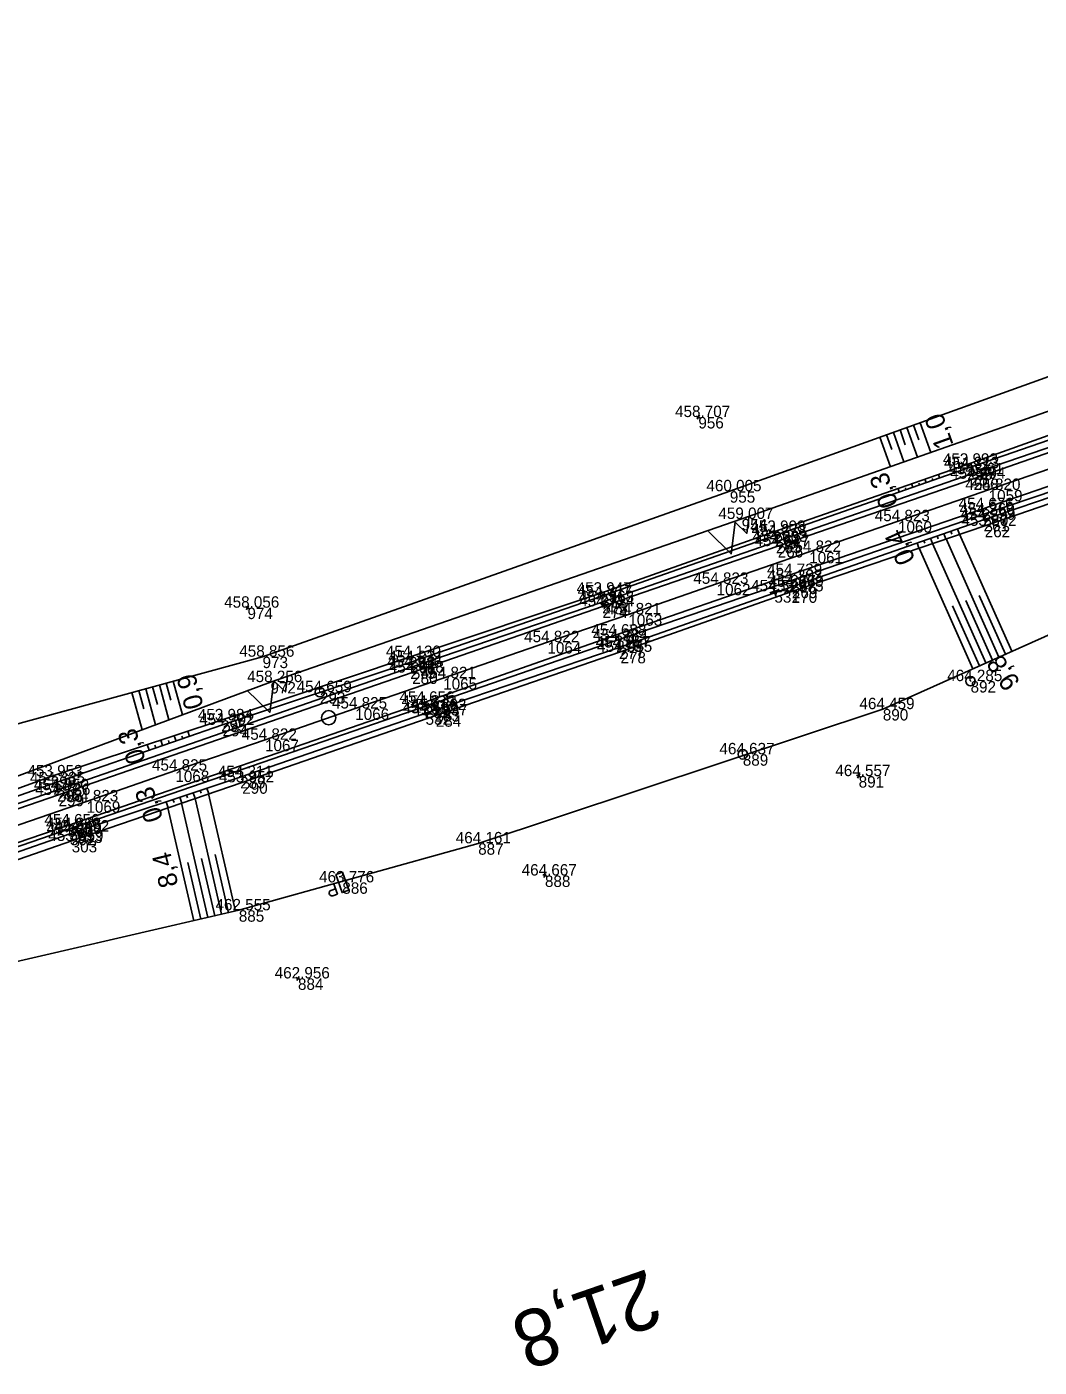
# Model space of a CAD drawing. Extents: x -751615 to -750797, y -1114905 to -1114561.
# Drawn here: x -751423 to -751316.4, y -1114841.6 to -1114700.6 of the extents above; entities that cross this region are included whole.
import ezdxf

# ---------------------------------------------------------------- set-up
doc = ezdxf.new("R2010")
doc.units = 0
for name, color, linetype in [('Vrstva 1', 7, 'Continuous'), ('Vrstva 33', 7, 'Continuous'), ('Vrstva 4', 7, 'Continuous'), ('Vrstva 48', 7, 'Continuous'), ('Vrstva 49', 7, 'Continuous'), ('Vrstva 50', 7, 'Continuous'), ('Vrstva 53', 7, 'Continuous'), ('Vrstva 60', 7, 'Continuous'), ('Vrstva 61', 7, 'Continuous'), ('Vrstva 7', 7, 'Continuous')]:
    doc.layers.add(name, color=color, linetype=linetype)

msp = doc.modelspace()

# ---------------------------------------------------------------- linework, layer by layer
at = {"layer": 'Vrstva 1'}
msp.add_lwpolyline([(-751207.29, -1114709.83), (-751216.51, -1114713.01), (-751226.43, -1114716.44), (-751236.32, -1114719.85), (-751245.85, -1114723.14), (-751255.29, -1114726.39), (-751264.7, -1114729.64), (-751273.96, -1114732.84), (-751283.46, -1114736.11), (-751293.11, -1114739.44), (-751302.88, -1114742.81), (-751312.19, -1114746.02), (-751321.76, -1114749.32), (-751331.3, -1114752.61), (-751340.65, -1114755.84), (-751350.4, -1114759.2), (-751359.69, -1114762.41), (-751368.21, -1114765.34), (-751379.18, -1114769.13), (-751388.44, -1114772.32), (-751397.94, -1114775.61), (-751407.38, -1114778.86), (-751416.74, -1114782.09), (-751426.63, -1114785.5)], dxfattribs=at)
at = {"layer": 'Vrstva 33'}
msp.add_lwpolyline([(-751389.12, -1114791.45), (-751389.82, -1114791.7), (-751390.48, -1114789.79), (-751389.77, -1114789.55)], close=True, dxfattribs=at)
for points in [[(-751390.8, -1114792.04), (-751390.97, -1114792.04), (-751391.14, -1114791.89), (-751391.18, -1114791.78), (-751391.14, -1114791.55), (-751391.01, -1114791.46)], [(-751391.01, -1114791.46), (-751390.51, -1114791.29)], [(-751390.72, -1114790.69), (-751390.31, -1114791.87)], [(-751390.31, -1114791.87), (-751390.8, -1114792.04)]]:
    msp.add_lwpolyline(points, dxfattribs=at)
at = {"layer": 'Vrstva 4'}
for points in [[(-751187.89, -1114700.58), (-751206.03, -1114707.04), (-751231.23, -1114715.6), (-751249.54, -1114721.97), (-751267.72, -1114728.47), (-751285.3, -1114734.54), (-751305.69, -1114741.51), (-751323.63, -1114747.67), (-751344.16, -1114754.78), (-751362.44, -1114761.12), (-751382.65, -1114768), (-751419.83, -1114780.91), (-751439.84, -1114787.75), (-751459.65, -1114794.56), (-751479.26, -1114801.4), (-751499.56, -1114808.3), (-751517.66, -1114814.61), (-751524.47, -1114817.14), (-751524.91, -1114817.65)], [(-751186.45, -1114705.27), (-751204.57, -1114711.26), (-751229.26, -1114719.97), (-751248.51, -1114726.39), (-751266.03, -1114732.59), (-751283.83, -1114738.73), (-751304.21, -1114745.77), (-751322.37, -1114751.9), (-751342.61, -1114758.9), (-751360.96, -1114765.17), (-751381.11, -1114772.12), (-751418.54, -1114785), (-751438.61, -1114791.91), (-751458.17, -1114798.66), (-751477.81, -1114805.42), (-751497.9, -1114812.48), (-751516.51, -1114818.69), (-751522.39, -1114820.61), (-751523.2, -1114820.52)], [(-751205.8, -1114707.6), (-751230.97, -1114716.26), (-751249.42, -1114722.68), (-751267.45, -1114728.87), (-751285.11, -1114734.87), (-751305.56, -1114741.94), (-751323.35, -1114748.14), (-751343.96, -1114755.23), (-751362.41, -1114761.58), (-751382.45, -1114768.54), (-751419.68, -1114781.41), (-751439.79, -1114788.3), (-751459.37, -1114795.06), (-751479.15, -1114801.88), (-751499.34, -1114808.87), (-751517.57, -1114815.16), (-751524.91, -1114817.65)], [(-751204.68, -1114710.75), (-751229.56, -1114719.28), (-751248.53, -1114725.94), (-751266.25, -1114732.04), (-751284.07, -1114738.15), (-751304.21, -1114745.08), (-751322.47, -1114751.34), (-751342.64, -1114758.27), (-751361.14, -1114764.64), (-751381.34, -1114771.71), (-751418.71, -1114784.62), (-751438.73, -1114791.47), (-751458.26, -1114798.22), (-751477.95, -1114805), (-751498.18, -1114811.91), (-751516.63, -1114818.24), (-751523.2, -1114820.52)]]:
    msp.add_lwpolyline(points, dxfattribs=at)
at = {"layer": 'Vrstva 48'}
for p, q in [((-751331.79, -1114743.26), (-751330.68, -1114746.37)), ((-751331.09, -1114743.01), (-751330.53, -1114744.56)), ((-751330.38, -1114742.75), (-751329.26, -1114745.87)), ((-751329.68, -1114742.5), (-751329.11, -1114744.06)), ((-751328.97, -1114742.25), (-751327.84, -1114745.38)), ((-751333.21, -1114743.77), (-751332.09, -1114746.87)), ((-751332.5, -1114743.52), (-751331.94, -1114745.07)), ((-751326.92, -1114748.05), (-751327.05, -1114747.68)), ((-751330.46, -1114749.29), (-751330.52, -1114749.1)), ((-751329.75, -1114749.04), (-751329.88, -1114748.67)), ((-751329.04, -1114748.8), (-751329.11, -1114748.61)), ((-751328.33, -1114748.55), (-751328.47, -1114748.17)), ((-751327.63, -1114748.3), (-751327.69, -1114748.11)), ((-751331.17, -1114749.54), (-751331.3, -1114749.16)), ((-751328.58, -1114754.66), (-751328.49, -1114754.93)), ((-751327.88, -1114754.41), (-751327.68, -1114754.97)), ((-751327.17, -1114754.16), (-751327.07, -1114754.45)), ((-751326.46, -1114753.91), (-751326.26, -1114754.49)), ((-751320.67, -1114766.91), (-751326.23, -1114754.48)), ((-751325.75, -1114753.67), (-751325.65, -1114753.96)), ((-751325.04, -1114753.42), (-751324.84, -1114754.01)), ((-751319.3, -1114766.3), (-751324.81, -1114753.99)), ((-751329.29, -1114754.9), (-751329.1, -1114755.45)), ((-751323.41, -1114768.14), (-751329.09, -1114755.45)), ((-751322.04, -1114767.53), (-751327.66, -1114754.96)), ((-751319.99, -1114766.61), (-751322.75, -1114760.42)), ((-751322.73, -1114767.83), (-751325.55, -1114761.52)), ((-751321.36, -1114767.22), (-751324.15, -1114760.97)), ((-751410.5, -1114770.24), (-751409.46, -1114774.03)), ((-751409.78, -1114770.04), (-751409.27, -1114771.9)), ((-751409.05, -1114769.84), (-751408.05, -1114773.51)), ((-751408.33, -1114769.64), (-751407.84, -1114771.44)), ((-751407.61, -1114769.45), (-751406.64, -1114772.98)), ((-751411.95, -1114770.64), (-751410.87, -1114774.55)), ((-751411.22, -1114770.44), (-751410.7, -1114772.36)), ((-751408.72, -1114776.23), (-751408.91, -1114775.65)), ((-751408.02, -1114775.98), (-751408.11, -1114775.7)), ((-751407.31, -1114775.74), (-751407.49, -1114775.18)), ((-751406.6, -1114775.49), (-751406.69, -1114775.22)), ((-751405.89, -1114775.25), (-751406.06, -1114774.71)), ((-751410.14, -1114776.72), (-751410.34, -1114776.12)), ((-751409.43, -1114776.47), (-751409.53, -1114776.18)), ((-751406.2, -1114781.41), (-751406.1, -1114781.72)), ((-751405.49, -1114781.18), (-751405.29, -1114781.79)), ((-751404.78, -1114780.94), (-751404.68, -1114781.24)), ((-751404.07, -1114780.7), (-751403.87, -1114781.3)), ((-751401.04, -1114793.64), (-751403.89, -1114781.31)), ((-751408.34, -1114782.13), (-751408.12, -1114782.77)), ((-751405.43, -1114794.65), (-751408.16, -1114782.78)), ((-751407.63, -1114781.89), (-751407.52, -1114782.21)), ((-751406.91, -1114781.65), (-751406.71, -1114782.28)), ((-751403.97, -1114794.31), (-751406.74, -1114782.29)), ((-751402.51, -1114793.98), (-751405.31, -1114781.8)), ((-751404.7, -1114794.48), (-751406.07, -1114788.51)), ((-751403.24, -1114794.14), (-751404.63, -1114788.09)), ((-751401.77, -1114793.81), (-751403.19, -1114787.68))]:
    msp.add_line(p, q, dxfattribs=at)
at = {"layer": 'Vrstva 49'}
for p, q in [((-751352.09, -1114741.76), (-751352.54, -1114741.54)), ((-751352.21, -1114741.42), (-751352.43, -1114741.87)), ((-751399.56, -1114761.82), (-751400.01, -1114761.6)), ((-751399.68, -1114761.49), (-751399.9, -1114761.93)), ((-751335.22, -1114779.55), (-751335.67, -1114779.33)), ((-751335.33, -1114779.21), (-751335.55, -1114779.66)), ((-751368.24, -1114790.01), (-751368.69, -1114789.79)), ((-751368.36, -1114789.67), (-751368.58, -1114790.12)), ((-751394.24, -1114800.84), (-751394.69, -1114800.62)), ((-751394.36, -1114800.51), (-751394.58, -1114800.96))]:
    msp.add_line(p, q, dxfattribs=at)
for points in [[(-751234.95, -1114713.28), (-751245.48, -1114717.14), (-751281.47, -1114726.53), (-751304.18, -1114733.33), (-751349.01, -1114749.46), (-751398.2, -1114766.87), (-751445.8, -1114779.91), (-751491.92, -1114801.09), (-751522.47, -1114813.15), (-751523.88, -1114811.23), (-751530.06, -1114804.52)], [(-751231.53, -1114714.48), (-751249.64, -1114721.46), (-751267.89, -1114727.82), (-751285.51, -1114733.95), (-751305.91, -1114740.8), (-751324, -1114747.03), (-751344.27, -1114754.11), (-751362.59, -1114760.52), (-751382.59, -1114767.44), (-751402.41, -1114774.04), (-751420.23, -1114780.2), (-751439.89, -1114787.15), (-751459.92, -1114794.04), (-751479.47, -1114800.49), (-751499.79, -1114807.5), (-751517.87, -1114814.1), (-751523.11, -1114815.97), (-751524.21, -1114815.64), (-751526.18, -1114811.44)], [(-751244.9, -1114718.57), (-751249.94, -1114720.63), (-751268.48, -1114726.93), (-751276.66, -1114729.62), (-751285.76, -1114733.33), (-751305.98, -1114740.17), (-751324.13, -1114746.66), (-751344.39, -1114753.73), (-751362.68, -1114760.23), (-751382.77, -1114766.9), (-751402.56, -1114773.56), (-751420.5, -1114779.46), (-751440.12, -1114786.64), (-751460.29, -1114793.37), (-751479.7, -1114799.99), (-751499.94, -1114807), (-751518.24, -1114813.43), (-751522.74, -1114814.82), (-751523.67, -1114814.11), (-751524.93, -1114811.32)], [(-751523.9, -1114821.95), (-751516.26, -1114819.37), (-751497.39, -1114813.06), (-751477.62, -1114806.13), (-751458.02, -1114799.12), (-751438.43, -1114792.47), (-751418.48, -1114785.51), (-751400.56, -1114779.53), (-751380.1, -1114772.49), (-751360.67, -1114765.9), (-751342.47, -1114759.51), (-751322.29, -1114752.46), (-751304.11, -1114746.3), (-751283.78, -1114739.21), (-751265.74, -1114733.22), (-751248.29, -1114727.04), (-751240.07, -1114724.3)], [(-751204.75, -1114724.61), (-751227.2, -1114725.51), (-751238.2, -1114726.49), (-751253.2, -1114735.38), (-751297.85, -1114756.71), (-751332.9, -1114772.39), (-751375.5, -1114786.51), (-751400.7, -1114793.56), (-751443.21, -1114803.36), (-751482.54, -1114812.28)], [(-751240.24, -1114725.65), (-751248.02, -1114728.05), (-751265.49, -1114734.04), (-751283.47, -1114739.99), (-751303.76, -1114746.77), (-751322.17, -1114753.1), (-751342.49, -1114760), (-751360.52, -1114766.36), (-751379.96, -1114773.04), (-751400.34, -1114780.09), (-751418.29, -1114786.26), (-751438.17, -1114793.17), (-751457.68, -1114799.96), (-751477.22, -1114807.06), (-751497.38, -1114813.97), (-751516.22, -1114820.45), (-751522.92, -1114822.93), (-751523.9, -1114821.95)], [(-751276.66, -1114729.62), (-751280.14, -1114730.3), (-751302.67, -1114736.54), (-751347.76, -1114752.37), (-751397.37, -1114769.54), (-751443.61, -1114786.7), (-751459.32, -1114792.11), (-751460.29, -1114793.37)]]:
    msp.add_lwpolyline(points, dxfattribs=at)
at = {"layer": 'Vrstva 50'}
for points in [[(-751347.01, -1114752.23), (-751347.23, -1114753.9), (-751348.43, -1114752.72), (-751348.87, -1114756.05), (-751351.26, -1114753.7)], [(-751395.58, -1114768.92), (-751395.8, -1114770.58), (-751397, -1114769.41), (-751397.44, -1114772.73), (-751399.84, -1114770.38)]]:
    msp.add_lwpolyline(points, dxfattribs=at)
at = {"layer": 'Vrstva 53'}
for p, q in [((-751323.61, -1114769.42), (-751323.71, -1114769.46)), ((-751347.6, -1114777.12), (-751347.69, -1114777.15))]:
    msp.add_line(p, q, dxfattribs=at)
for centre in [(-751323.66, -1114769.44), (-751347.64, -1114777.14)]:
    msp.add_circle(centre, 0.499, dxfattribs=at)
at = {"layer": 'Vrstva 60'}
for p, q in [((-751352.32, -1114741.65), (-751352.32, -1114741.65)), ((-751324.13, -1114746.66), (-751324.13, -1114746.66)), ((-751324, -1114747.03), (-751324, -1114747.03)), ((-751323.63, -1114747.67), (-751323.63, -1114747.67)), ((-751323.35, -1114748.14), (-751323.35, -1114748.14)), ((-751349.01, -1114749.46), (-751349.01, -1114749.46)), ((-751321.76, -1114749.32), (-751321.76, -1114749.32)), ((-751322.47, -1114751.34), (-751322.47, -1114751.34)), ((-751322.37, -1114751.9), (-751322.37, -1114751.9)), ((-751347.76, -1114752.37), (-751347.76, -1114752.37)), ((-751331.3, -1114752.61), (-751331.3, -1114752.61)), ((-751322.29, -1114752.46), (-751322.29, -1114752.46)), ((-751322.17, -1114753.1), (-751322.17, -1114753.1)), ((-751344.39, -1114753.73), (-751344.39, -1114753.73)), ((-751344.27, -1114754.11), (-751344.27, -1114754.11)), ((-751344.16, -1114754.78), (-751344.16, -1114754.78)), ((-751343.96, -1114755.23), (-751343.96, -1114755.23)), ((-751340.65, -1114755.84), (-751340.65, -1114755.84)), ((-751342.64, -1114758.27), (-751342.64, -1114758.27)), ((-751342.61, -1114758.9), (-751342.61, -1114758.9)), ((-751362.68, -1114760.23), (-751362.68, -1114760.23)), ((-751350.4, -1114759.2), (-751350.4, -1114759.2)), ((-751344.31, -1114759.98), (-751344.31, -1114759.98)), ((-751342.49, -1114760), (-751342.49, -1114760)), ((-751342.47, -1114759.51), (-751342.47, -1114759.51)), ((-751399.79, -1114761.71), (-751399.79, -1114761.71)), ((-751362.59, -1114760.52), (-751362.59, -1114760.52)), ((-751362.44, -1114761.12), (-751362.44, -1114761.12)), ((-751362.41, -1114761.58), (-751362.41, -1114761.58)), ((-751359.69, -1114762.41), (-751359.69, -1114762.41)), ((-751361.14, -1114764.64), (-751361.14, -1114764.64)), ((-751368.21, -1114765.34), (-751368.21, -1114765.34)), ((-751360.96, -1114765.17), (-751360.96, -1114765.17)), ((-751360.67, -1114765.9), (-751360.67, -1114765.9)), ((-751398.2, -1114766.87), (-751398.2, -1114766.87)), ((-751382.77, -1114766.9), (-751382.77, -1114766.9)), ((-751382.59, -1114767.44), (-751382.59, -1114767.44)), ((-751360.52, -1114766.36), (-751360.52, -1114766.36)), ((-751382.65, -1114768), (-751382.65, -1114768)), ((-751382.45, -1114768.54), (-751382.45, -1114768.54)), ((-751397.37, -1114769.54), (-751397.37, -1114769.54)), ((-751379.18, -1114769.13), (-751379.18, -1114769.13)), ((-751323.66, -1114769.44), (-751323.66, -1114769.44)), ((-751392.16, -1114770.6), (-751392.16, -1114770.6)), ((-751381.34, -1114771.71), (-751381.34, -1114771.71)), ((-751388.44, -1114772.32), (-751388.44, -1114772.32)), ((-751381.11, -1114772.12), (-751381.11, -1114772.12)), ((-751381.04, -1114772.83), (-751381.04, -1114772.83)), ((-751380.1, -1114772.49), (-751380.1, -1114772.49)), ((-751379.96, -1114773.04), (-751379.96, -1114773.04)), ((-751332.9, -1114772.39), (-751332.9, -1114772.39)), ((-751402.56, -1114773.56), (-751402.56, -1114773.56)), ((-751402.41, -1114774.04), (-751402.41, -1114774.04)), ((-751397.94, -1114775.61), (-751397.94, -1114775.61)), ((-751347.64, -1114777.14), (-751347.64, -1114777.14)), ((-751420.5, -1114779.46), (-751420.5, -1114779.46)), ((-751407.38, -1114778.86), (-751407.38, -1114778.86)), ((-751400.56, -1114779.53), (-751400.56, -1114779.53)), ((-751400.34, -1114780.09), (-751400.34, -1114780.09)), ((-751335.44, -1114779.44), (-751335.44, -1114779.44)), ((-751420.23, -1114780.2), (-751420.23, -1114780.2)), ((-751419.83, -1114780.91), (-751419.83, -1114780.91)), ((-751419.68, -1114781.41), (-751419.68, -1114781.41)), ((-751416.74, -1114782.09), (-751416.74, -1114782.09)), ((-751418.71, -1114784.62), (-751418.71, -1114784.62)), ((-751418.54, -1114785), (-751418.54, -1114785)), ((-751418.48, -1114785.51), (-751418.48, -1114785.51)), ((-751417.71, -1114785.27), (-751417.71, -1114785.27)), ((-751418.29, -1114786.26), (-751418.29, -1114786.26)), ((-751375.5, -1114786.51), (-751375.5, -1114786.51)), ((-751368.47, -1114789.9), (-751368.47, -1114789.9)), ((-751389.8, -1114790.62), (-751389.8, -1114790.62)), ((-751400.7, -1114793.56), (-751400.7, -1114793.56)), ((-751394.47, -1114800.73), (-751394.47, -1114800.73))]:
    msp.add_line(p, q, dxfattribs=at)
at = {"layer": 'Vrstva 7'}
for p, q in [((-751343.84, -1114759.82), (-751344.78, -1114760.14)), ((-751344.15, -1114760.45), (-751344.47, -1114759.51)), ((-751392.11, -1114770.58), (-751392.2, -1114770.61)), ((-751380.57, -1114772.67), (-751381.51, -1114772.99)), ((-751380.88, -1114773.3), (-751381.2, -1114772.36)), ((-751417.23, -1114785.11), (-751418.18, -1114785.44)), ((-751417.54, -1114785.75), (-751417.87, -1114784.8))]:
    msp.add_line(p, q, dxfattribs=at)
for centre, radius in [((-751392.16, -1114770.6), 0.5), ((-751391.23, -1114773.29), 0.75)]:
    msp.add_circle(centre, radius, dxfattribs=at)

# ---------------------------------------------------------------- texts
at = {"layer": 'Vrstva 48'}
for s, rotation, p in [('1,0', 109.7893, (-751325.42, -1114744.57)), ('0,3', 109.2497, (-751331.25, -1114750.82)), ('0,4', 114.252, (-751329.44, -1114756.65)), ('9,8', 123.7534, (-751318.37, -1114769.56)), ('0,9', 105.316, (-751404.38, -1114772.09)), ('0,3', 108.2047, (-751410.46, -1114777.78)), ('0,3', 108.434, (-751408.63, -1114783.9)), ('8,4', 103.9571, (-751407.05, -1114790.89))]:
    msp.add_text(s, height=2, rotation=rotation, dxfattribs=at).set_placement(p)
at = {"layer": 'Vrstva 60'}
for s, p in [('956', (-751352.32, -1114742.85)), ('255', (-751324.13, -1114747.86)), ('256', (-751324, -1114748.24)), ('257', (-751323.63, -1114748.87)), ('258', (-751323.35, -1114749.33)), ('955', (-751349.01, -1114750.66)), ('1059', (-751321.76, -1114750.52)), ('259', (-751322.47, -1114752.54)), ('260', (-751322.37, -1114753.1)), ('954', (-751347.76, -1114753.57)), ('1060', (-751331.3, -1114753.81)), ('261', (-751322.29, -1114753.66)), ('262', (-751322.17, -1114754.3)), ('263', (-751344.39, -1114754.93)), ('264', (-751344.27, -1114755.31)), ('265', (-751344.16, -1114755.99)), ('266', (-751343.96, -1114756.43)), ('1061', (-751340.65, -1114757.04)), ('267', (-751342.64, -1114759.47)), ('268', (-751342.61, -1114760.1)), ('271', (-751362.68, -1114761.43)), ('1062', (-751350.4, -1114760.4)), ('531', (-751344.31, -1114761.18)), ('270', (-751342.49, -1114761.2)), ('269', (-751342.47, -1114760.71)), ('974', (-751399.79, -1114762.91)), ('272', (-751362.59, -1114761.72)), ('273', (-751362.44, -1114762.32)), ('274', (-751362.41, -1114762.78)), ('1063', (-751359.69, -1114763.61)), ('275', (-751361.14, -1114765.84)), ('1064', (-751368.21, -1114766.54)), ('276', (-751360.96, -1114766.37)), ('277', (-751360.67, -1114767.1)), ('973', (-751398.2, -1114768.07)), ('292', (-751382.77, -1114768.1)), ('291', (-751382.59, -1114768.64)), ('278', (-751360.52, -1114767.56)), ('279', (-751382.65, -1114769.2)), ('280', (-751382.45, -1114769.74)), ('972', (-751397.37, -1114770.74)), ('1065', (-751379.18, -1114770.33)), ('892', (-751323.66, -1114770.64)), ('293', (-751392.16, -1114771.8)), ('281', (-751381.34, -1114772.91)), ('1066', (-751388.44, -1114773.52)), ('282', (-751381.11, -1114773.32)), ('532', (-751381.04, -1114774.03)), ('283', (-751380.1, -1114773.69)), ('284', (-751379.96, -1114774.24)), ('890', (-751332.9, -1114773.58)), ('295', (-751402.56, -1114774.76)), ('294', (-751402.41, -1114775.25)), ('1067', (-751397.94, -1114776.81)), ('889', (-751347.64, -1114778.34)), ('296', (-751420.5, -1114780.66)), ('297', (-751420.23, -1114781.4)), ('1068', (-751407.38, -1114780.06)), ('289', (-751400.56, -1114780.73)), ('290', (-751400.34, -1114781.29)), ('891', (-751335.44, -1114780.64)), ('298', (-751419.83, -1114782.11)), ('299', (-751419.68, -1114782.61)), ('1069', (-751416.74, -1114783.29)), ('300', (-751418.71, -1114785.82)), ('301', (-751418.54, -1114786.2)), ('302', (-751418.48, -1114786.71)), ('533', (-751417.71, -1114786.47)), ('303', (-751418.29, -1114787.46)), ('887', (-751375.5, -1114787.71)), ('888', (-751368.47, -1114791.1)), ('886', (-751389.8, -1114791.82)), ('885', (-751400.7, -1114794.76)), ('884', (-751394.47, -1114801.93))]:
    msp.add_text(s, height=1.2, dxfattribs=at).set_placement(p)
at = {"layer": 'Vrstva 61'}
for s, p in [('458.707', (-751354.77, -1114741.65)), ('453.993', (-751326.58, -1114746.66)), ('454.313', (-751326.45, -1114747.03)), ('454.361', (-751325.99, -1114747.67)), ('454.694', (-751325.8, -1114748.14)), ('460.005', (-751351.47, -1114749.46)), ('454.820', (-751324.21, -1114749.32)), ('454.676', (-751324.92, -1114751.34)), ('459.007', (-751350.21, -1114752.37)), ('454.823', (-751333.75, -1114752.61)), ('454.260', (-751324.82, -1114751.9)), ('454.239', (-751324.74, -1114752.46)), ('453.872', (-751324.62, -1114753.1)), ('453.908', (-751346.84, -1114753.73)), ('454.278', (-751346.72, -1114754.11)), ('454.303', (-751346.62, -1114754.78)), ('454.627', (-751346.41, -1114755.23)), ('454.822', (-751343.1, -1114755.84)), ('454.739', (-751345.09, -1114758.27)), ('453.947', (-751365.14, -1114760.23)), ('454.823', (-751352.85, -1114759.2)), ('454.523', (-751346.76, -1114759.98)), ('454.303', (-751345.06, -1114758.9)), ('453.975', (-751344.94, -1114760)), ('454.269', (-751344.92, -1114759.51)), ('454.317', (-751365.04, -1114760.52)), ('454.363', (-751364.89, -1114761.12)), ('454.724', (-751364.86, -1114761.58)), ('458.056', (-751402.24, -1114761.71)), ('454.821', (-751362.04, -1114762.41)), ('454.822', (-751370.66, -1114765.34)), ('454.688', (-751363.59, -1114764.64)), ('454.284', (-751363.42, -1114765.17)), ('458.856', (-751400.65, -1114766.87)), ('454.130', (-751385.22, -1114766.9)), ('454.257', (-751363.12, -1114765.9)), ('454.055', (-751362.98, -1114766.36)), ('454.346', (-751385.1, -1114768)), ('454.331', (-751384.95, -1114767.44)), ('454.688', (-751384.91, -1114768.54)), ('458.256', (-751399.82, -1114769.54)), ('454.821', (-751381.54, -1114769.13)), ('464.285', (-751326.12, -1114769.44)), ('454.659', (-751394.61, -1114770.6)), ('454.825', (-751390.89, -1114772.32)), ('454.656', (-751383.79, -1114771.71)), ('454.373', (-751383.57, -1114772.12)), ('454.462', (-751383.49, -1114772.83)), ('454.302', (-751382.54, -1114772.49)), ('464.459', (-751335.36, -1114772.39)), ('453.984', (-751405.01, -1114773.56)), ('454.302', (-751404.86, -1114774.04)), ('453.997', (-751382.41, -1114773.04)), ('454.822', (-751400.39, -1114775.61)), ('464.637', (-751350.1, -1114777.14)), ('453.953', (-751422.95, -1114779.46)), ('454.825', (-751409.84, -1114778.86)), ('454.311', (-751402.91, -1114779.53)), ('464.557', (-751337.9, -1114779.44)), ('454.335', (-751422.69, -1114780.2)), ('454.350', (-751422.28, -1114780.91)), ('453.952', (-751402.79, -1114780.09)), ('454.736', (-751422.13, -1114781.41)), ('454.823', (-751419.19, -1114782.09)), ('454.656', (-751421.17, -1114784.62)), ('454.368', (-751420.99, -1114785)), ('454.280', (-751420.93, -1114785.51)), ('454.492', (-751420.15, -1114785.27)), ('453.959', (-751420.75, -1114786.26)), ('464.161', (-751377.86, -1114786.51)), ('463.776', (-751392.25, -1114790.62)), ('464.667', (-751370.92, -1114789.9)), ('462.555', (-751403.15, -1114793.56)), ('462.956', (-751396.92, -1114800.73))]:
    msp.add_text(s, height=1.2, dxfattribs=at).set_placement(p)
at = {"layer": 'Vrstva 7'}
msp.add_text('21,8', height=6, rotation=199.0653, dxfattribs=at).set_placement((-751357.63, -1114831.25))

doc.saveas('drawing.dxf')
